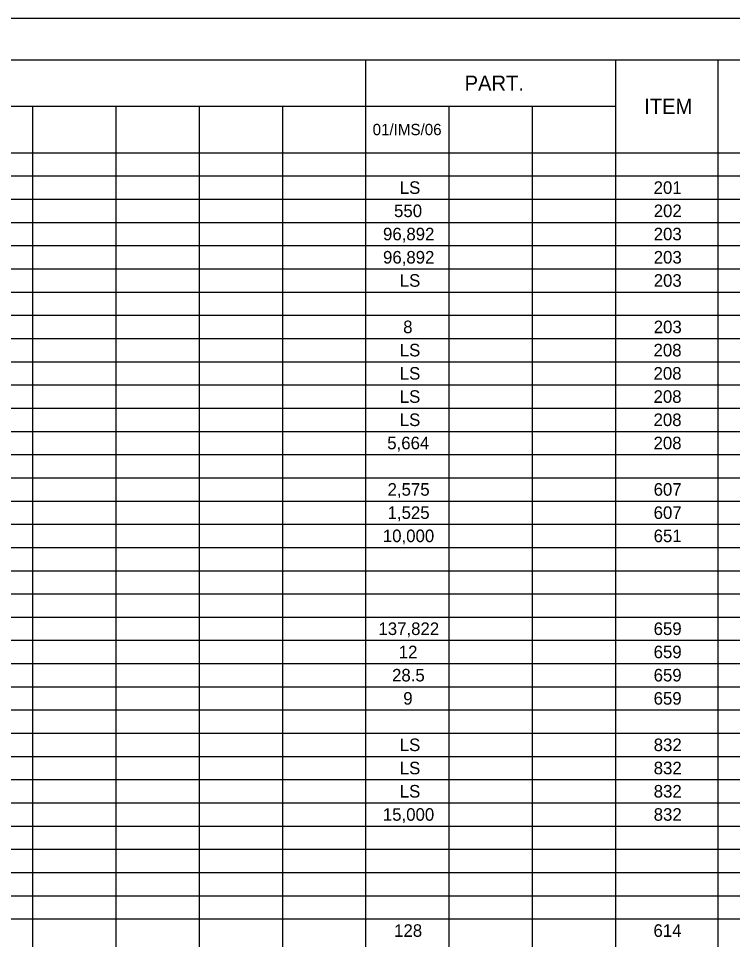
# Model space of a CAD drawing. Extents: x 0 to 34, y 0 to 22.
# Drawn here: x 8.36 to 16.98, y 10.89 to 22 of the extents above; entities that cross this region are included whole.
import ezdxf

# ---------------------------------------------------------------- set-up
doc = ezdxf.new("R2010")
doc.units = 0
for name, color, linetype in [('SH_Border', 7, 'Continuous'), ('SH_Cut_Line', 7, 'Continuous'), ('SH_Text', 7, 'Continuous')]:
    doc.layers.add(name, color=color, linetype=linetype)

msp = doc.modelspace()

# ---------------------------------------------------------------- linework, layer by layer
at = {"layer": 'SH_Border'}
msp.add_lwpolyline([(1.5, 21.5), (33.5, 21.5), (33.5, 0.5), (1.5, 0.5)], close=True, dxfattribs=at)
at = {"layer": 'SH_Cut_Line'}
msp.add_lwpolyline([(0, 0), (34, 0), (34, 22), (0, 22)], close=True, dxfattribs=at)
at = {"layer": 'SH_Text'}
for p, q in [((1.5, 21.5), (32, 21.5)), ((12.55, 21.5), (12.55, 0.5)), ((15.564, 21.5), (15.564, 0.5)), ((16.799, 21.5), (16.799, 0.5)), ((1.5, 20.94), (15.564, 20.94)), ((8.532, 20.94), (8.532, 0.5)), ((9.537, 20.94), (9.537, 0.5)), ((10.541, 20.94), (10.541, 0.5)), ((11.546, 20.94), (11.546, 0.5)), ((13.555, 20.94), (13.555, 0.5)), ((14.56, 20.94), (14.56, 0.5)), ((1.5, 20.38), (32, 20.38)), ((1.5, 20.1), (32, 20.1)), ((1.5, 19.82), (32, 19.82)), ((1.5, 19.54), (32, 19.54)), ((1.5, 19.26), (32, 19.26)), ((1.5, 18.98), (32, 18.98)), ((1.5, 18.7), (32, 18.7)), ((1.5, 18.42), (32, 18.42)), ((1.5, 18.14), (32, 18.14)), ((1.5, 17.86), (32, 17.86)), ((1.5, 17.58), (32, 17.58)), ((1.5, 17.3), (32, 17.3)), ((1.5, 17.02), (32, 17.02)), ((1.5, 16.74), (32, 16.74)), ((1.5, 16.46), (32, 16.46)), ((1.5, 16.18), (32, 16.18)), ((1.5, 15.9), (32, 15.9)), ((1.5, 15.62), (32, 15.62)), ((1.5, 15.34), (32, 15.34)), ((1.5, 15.06), (32, 15.06)), ((1.5, 14.78), (32, 14.78)), ((1.5, 14.5), (32, 14.5)), ((1.5, 14.22), (32, 14.22)), ((1.5, 13.94), (32, 13.94)), ((1.5, 13.66), (32, 13.66)), ((1.5, 13.38), (32, 13.38)), ((1.5, 13.1), (32, 13.1)), ((1.5, 12.82), (32, 12.82)), ((1.5, 12.54), (32, 12.54)), ((1.5, 12.26), (32, 12.26)), ((1.5, 11.98), (32, 11.98)), ((1.5, 11.7), (32, 11.7)), ((1.5, 11.42), (32, 11.42)), ((1.5, 11.14), (32, 11.14))]:
    msp.add_line(p, q, dxfattribs=at)

# ---------------------------------------------------------------- texts
for s, height, p in [('PART.', 0.1818, (13.744, 21.129)), ('ITEM', 0.1818, (15.91, 20.849)), ('01/IMS/06', 0.1364, (12.635, 20.592)), ('LS', 0.1515, (12.962, 19.884)), ('201', 0.1515, (16.024, 19.884)), ('550', 0.1515, (12.893, 19.604)), ('202', 0.1515, (16.025, 19.604)), ('96,892', 0.1515, (12.76, 19.324)), ('203', 0.1515, (16.025, 19.324)), ('96,892', 0.1515, (12.76, 19.044)), ('203', 0.1515, (16.025, 19.044)), ('LS', 0.1515, (12.962, 18.764)), ('203', 0.1515, (16.025, 18.764)), ('8', 0.152, (13.003, 18.204)), ('203', 0.1515, (16.025, 18.204)), ('LS', 0.1515, (12.962, 17.924)), ('208', 0.1515, (16.023, 17.924)), ('LS', 0.1515, (12.962, 17.644)), ('208', 0.1515, (16.023, 17.644)), ('LS', 0.1515, (12.962, 17.364)), ('208', 0.1515, (16.023, 17.364)), ('LS', 0.1515, (12.962, 17.084)), ('208', 0.1515, (16.023, 17.084)), ('5,664', 0.1515, (12.811, 16.804)), ('208', 0.1515, (16.023, 16.804)), ('2,575', 0.1515, (12.815, 16.244)), ('607', 0.1515, (16.024, 16.244)), ('1,525', 0.1515, (12.815, 15.964)), ('607', 0.1515, (16.024, 15.964)), ('10,000', 0.1515, (12.758, 15.684)), ('651', 0.1515, (16.024, 15.684)), ('137,822', 0.1515, (12.705, 14.564)), ('659', 0.1515, (16.024, 14.564)), ('12', 0.1515, (12.95, 14.284)), ('659', 0.1515, (16.024, 14.284)), ('28.5', 0.1515, (12.869, 14.004)), ('659', 0.1515, (16.024, 14.004)), ('9', 0.152, (13.004, 13.724)), ('659', 0.1515, (16.024, 13.724)), ('LS', 0.1515, (12.962, 13.164)), ('832', 0.1515, (16.025, 13.164)), ('LS', 0.1515, (12.962, 12.884)), ('832', 0.1515, (16.025, 12.884)), ('LS', 0.1515, (12.962, 12.604)), ('832', 0.1515, (16.025, 12.604)), ('15,000', 0.1515, (12.758, 12.324)), ('832', 0.1515, (16.025, 12.324)), ('128', 0.1515, (12.894, 10.924)), ('614', 0.1515, (16.022, 10.924))]:
    msp.add_text(s, height=height, dxfattribs=at).set_placement(p)

doc.saveas('drawing.dxf')
